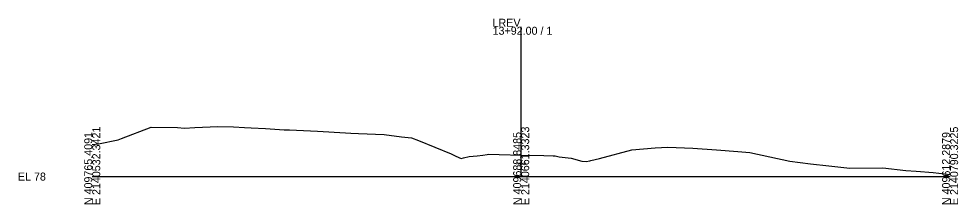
# Model space of a CAD drawing. Extents: x -14026 to 1303, y -10 to 9533.
# Drawn here: x -25.7 to 302.8, y -9.7 to 55.3 of the extents above; entities that cross this region are included whole.
import ezdxf

# ---------------------------------------------------------------- set-up
doc = ezdxf.new("R2010")
doc.units = 0
for name, color, linetype in [('Default', 7, 'Continuous'), ('Exist Cross Section Cell', 7, 'Continuous'), ('Exist XS Center Line Elevation Label', 7, 'Continuous'), ('Exist XS Ground Line', 7, 'Continuous')]:
    doc.layers.add(name, color=color, linetype=linetype)

msp = doc.modelspace()

# ---------------------------------------------------------------- linework, layer by layer
at = {"layer": 'Exist Cross Section Cell'}
for p, q in [((150, 0), (150, 52.46)), ((0, 0), (150, 0)), ((150, 0), (300, 0))]:
    msp.add_line(p, q, dxfattribs=at)
at = {"layer": 'Exist XS Ground Line'}
msp.add_lwpolyline([(0, 11.2), (2.17, 11.43), (9.01, 12.81), (10.23, 13.32), (20.64, 17.35), (29.83, 17.22), (32.27, 16.96), (35.85, 17.23), (43.9, 17.49), (49.42, 17.36), (53.26, 17.17), (55.53, 17.08), (60.56, 16.79), (67.16, 16.42), (69.02, 16.32), (78.79, 15.89), (88.61, 15.35), (90.42, 15.24), (93.07, 15.09), (102.05, 14.69), (108.2, 13.89), (111.64, 13.52), (114.06, 12.63), (125.47, 7.99), (127.18, 7.15), (129, 6.28), (129.86, 6.53), (131.83, 7.08), (134.62, 7.31), (136.59, 7.47), (138.08, 7.68), (138.74, 7.79), (142.32, 7.68), (150.1, 7.49), (157.96, 7.38), (161.24, 7.29), (161.85, 7.22), (163.34, 6.93), (165.35, 6.7), (167.53, 6.41), (171.25, 5.41), (172.72, 5.28), (174.02, 5.52), (174.33, 5.64), (177.41, 6.35), (188.66, 9.39), (196.89, 10.11), (201.28, 10.35), (209.99, 9.96), (218.35, 9.4), (225.77, 8.76), (229.98, 8.37), (237.01, 6.92), (243.9, 5.42), (251.16, 4.46), (257.61, 3.79), (264.96, 2.89), (276.5, 3), (284.55, 2.13), (288.13, 1.88), (294.1, 1.42), (300, 0.74)], dxfattribs=at)

# ---------------------------------------------------------------- texts
at = {"layer": 'Default'}
msp.add_text('-', height=0.0001, dxfattribs=at).set_placement((0, 0))
at = {"layer": 'Exist Cross Section Cell'}
for s, p in [('13+92.00 / 1', (140, 49.66)), ('LREV', (140, 52.46)), ('EL 78', (-26, -1.4))]:
    msp.add_text(s, height=2.8, dxfattribs=at).set_placement(p)
for s, p in [('E 2140532.3421', (2.8, -10)), ('E 2140661.3323', (152.8, -10)), ('E 2140790.3225', (302.8, -10)), ('N 409765.4091', (0, -10)), ('N 409688.8485', (150, -10)), ('N 409612.2879', (300, -10))]:
    msp.add_text(s, height=2.8, rotation=90, dxfattribs=at).set_placement(p)
at = {"layer": 'Exist XS Center Line Elevation Label'}
msp.add_text('85.49', height=1, dxfattribs=at).set_placement((148.26, 3.99))

doc.saveas('drawing.dxf')
